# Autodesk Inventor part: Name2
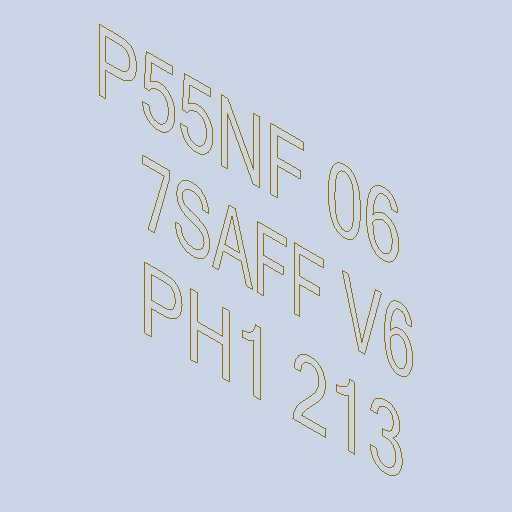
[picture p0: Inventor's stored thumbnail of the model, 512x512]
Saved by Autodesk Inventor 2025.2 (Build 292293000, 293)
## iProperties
Created: 2025-04
Part Number: Name2
Material: Generic
Description: PART--DESC
Document SubType Name: Modeling
Designer: BennF
Density: 1 g/cm^3
Appearance: Default
Author: BennF
Revision Number: NONE
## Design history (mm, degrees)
feature "Composite1"
body "Srf1"
